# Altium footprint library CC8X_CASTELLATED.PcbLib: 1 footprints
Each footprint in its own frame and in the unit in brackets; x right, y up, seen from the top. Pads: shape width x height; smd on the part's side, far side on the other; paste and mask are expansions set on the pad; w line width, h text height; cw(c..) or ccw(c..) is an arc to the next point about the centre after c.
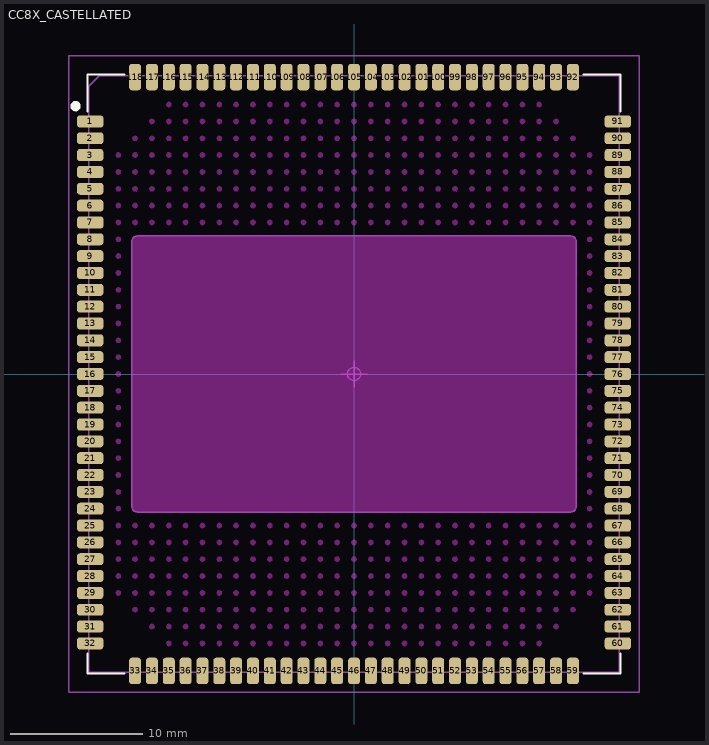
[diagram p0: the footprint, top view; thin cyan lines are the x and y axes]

## CC8X_CASTELLATED [mm]
height 1.55
pads (118):
  rrect50% 2x0.9 smd: 1(-19.9,19.05) 2(-19.9,17.78) 3(-19.9,16.51) 4(-19.9,15.24) 5(-19.9,13.97) 6(-19.9,12.7) 7(-19.9,11.43) 8(-19.9,10.16) 9(-19.9,8.89) 10(-19.9,7.62) 11(-19.9,6.35) 12(-19.9,5.08) 13(-19.9,3.81) 14(-19.9,2.54) 15(-19.9,1.27) 16(-19.9,0) 17(-19.9,-1.27) 18(-19.9,-2.54) 19(-19.9,-3.81) 20(-19.9,-5.08) 21(-19.9,-6.35) 22(-19.9,-7.62) 23(-19.9,-8.89) 24(-19.9,-10.16) 25(-19.9,-11.43) 26(-19.9,-12.7) 27(-19.9,-13.97) 28(-19.9,-15.24) 29(-19.9,-16.51) 30(-19.9,-17.78) 31(-19.9,-19.05) 32(-19.9,-20.32) 60(19.9,-20.32) 61(19.9,-19.05) 62(19.9,-17.78) 63(19.9,-16.51) 64(19.9,-15.24) 65(19.9,-13.97) 66(19.9,-12.7) 67(19.9,-11.43) 68(19.9,-10.16) 69(19.9,-8.89) 70(19.9,-7.62) 71(19.9,-6.35) 72(19.9,-5.08) 73(19.9,-3.81) 74(19.9,-2.54) 75(19.9,-1.27) 76(19.9,0) 77(19.9,1.27) 78(19.9,2.54) 79(19.9,3.81) 80(19.9,5.08) 81(19.9,6.35) 82(19.9,7.62) 83(19.9,8.89) 84(19.9,10.16) 85(19.9,11.43) 86(19.9,12.7) 87(19.9,13.97) 88(19.9,15.24) 89(19.9,16.51) 90(19.9,17.78) 91(19.9,19.05)
  rrect50% 0.9x2 smd: 33(-16.51,-22.4) 34(-15.24,-22.4) 35(-13.97,-22.4) 36(-12.7,-22.4) 37(-11.43,-22.4) 38(-10.16,-22.4) 39(-8.89,-22.4) 40(-7.62,-22.4) 41(-6.35,-22.4) 42(-5.08,-22.4) 43(-3.81,-22.4) 44(-2.54,-22.4) 45(-1.27,-22.4) 46(0,-22.4) 47(1.27,-22.4) 48(2.54,-22.4) 49(3.81,-22.4) 50(5.08,-22.4) 51(6.35,-22.4) 52(7.62,-22.4) 53(8.89,-22.4) 54(10.16,-22.4) 55(11.43,-22.4) 56(12.7,-22.4) 57(13.97,-22.4) 58(15.24,-22.4) 59(16.51,-22.4) 92(16.51,22.4) 93(15.24,22.4) 94(13.97,22.4) 95(12.7,22.4) 96(11.43,22.4) 97(10.16,22.4) 98(8.89,22.4) 99(7.62,22.4) 100(6.35,22.4) 101(5.08,22.4) 102(3.81,22.4) 103(2.54,22.4) 104(1.27,22.4) 105(0,22.4) 106(-1.27,22.4) 107(-2.54,22.4) 108(-3.81,22.4) 109(-5.08,22.4) 110(-6.35,22.4) 111(-7.62,22.4) 112(-8.89,22.4) 113(-10.16,22.4) 114(-11.43,22.4) 115(-12.7,22.4) 116(-13.97,22.4) 117(-15.24,22.4) 118(-16.51,22.4)
Top Layer keep-out:
  drawing of 474 lines, arcs and shapes, not listed
Top Overlay:
  circle w0.4: c-21,20.2 r0.182
  lines w0.15: -20.1,-21.1 -20.1,-22.6 -17.3,-22.6 ; -20.1,19.8 -20.1,22.6 -17.3,22.6 ; 17.3,-22.6 20.1,-22.6 20.1,-21.1 ; 17.3,22.6 20.1,22.6 20.1,19.8
Keep-Out Layer:
  board cut-out: 16.78,9.93 16.78,10.029 16.704,10.213 16.563,10.354 16.379,10.43 16.28,10.43 -16.28,10.43 -16.379,10.43 -16.563,10.354 -16.704,10.213 -16.78,10.029 -16.78,9.93 -16.78,-9.93 -16.78,-10.029 -16.704,-10.213 -16.563,-10.354 -16.379,-10.43 -16.28,-10.43 16.28,-10.43 16.379,-10.43 16.563,-10.354 16.704,-10.213 16.78,-10.029 16.78,-9.93
Board Outline:
  lines w0.1: 16.28,-10.43 ccw(c16.28,-9.93) 16.78,-9.93 ; 16.28,-10.43 ccw(c16.28,-9.93) 16.78,-9.93 ; 16.28,-10.43 -16.28,-10.43 cw(c-16.28,-9.93) -16.78,-9.93 -16.78,9.93 cw(c-16.28,9.93) -16.28,10.43 16.28,10.43 cw(c16.28,9.93) 16.78,9.93 16.78,-9.93
Assembly Top:
  lines w0.102: -20,-22.5 20,-22.5 20,22.5 -19.2,22.5 -20,21.7 -20,-22.5
  text ".Designator" at -1.25,-0.5 h1
Courtyard Top:
  circle w0.1: c0,0 r0.5
  lines w0.1: -1,0 1,0 ; 0,-1 0,1 ; -21.5,-24 21.5,-24 21.5,24 -21.5,24 -21.5,-24
3D body "30015412-01_A_CC8X.step": height 4.07, standoff -0.9, extent -20,-22.5 20,22.5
